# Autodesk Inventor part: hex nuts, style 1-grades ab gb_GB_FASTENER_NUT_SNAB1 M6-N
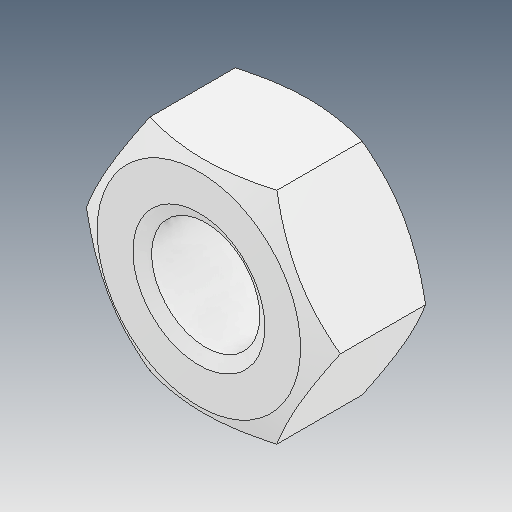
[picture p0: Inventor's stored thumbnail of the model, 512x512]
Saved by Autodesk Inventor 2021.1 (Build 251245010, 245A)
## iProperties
Created: 2021-05
Part Number: hex nuts, style 1-grades ab gb_GB_FASTENER_NUT_SNAB1 M6-N
Material: Ogólny
Document SubType Name: Modeling
Designer: user
Density: 1 g/cm^3
Appearance: Domyślna
Author: user
Revision Number: ÈÎºÎ
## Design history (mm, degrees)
feature "ÊäÈë1"
node "Bryła1"
